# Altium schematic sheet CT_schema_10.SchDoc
size 226 x 144 mm
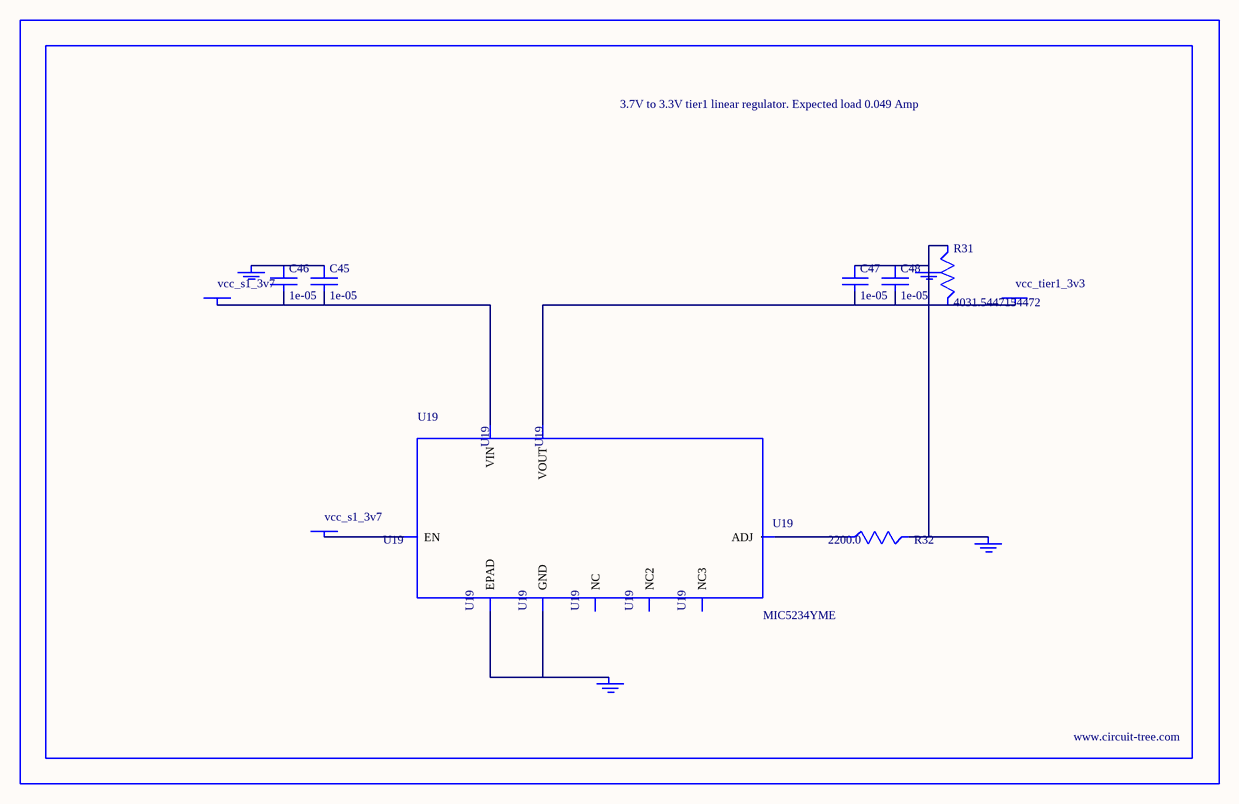
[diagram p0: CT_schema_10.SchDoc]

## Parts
BORDER9  (no value)
C45  1e-05  [C1210]
C46  1e-05  [C1210]
C47  1e-05  [C1210]
C48  1e-05  [C1210]
GND_INSTANCE_9_0  (no value)
GND_INSTANCE_9_1  (no value)
GND_INSTANCE_9_2  (no value)
GND_INSTANCE_9_3  (no value)
POWER_INSTANCE_9_0  vcc_tier1_3v3
POWER_INSTANCE_9_1  vcc_s1_3v7
POWER_INSTANCE_9_2  vcc_s1_3v7
R31  4031.5447154472  [R0603]
R32  2200.0  [R0603]
U19  MIC5234YME  [SOIC-8_EP]

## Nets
NetC45_1: C45.1 C46.1 GND_INSTANCE_9_3.0(GND)
NetC45_2: C45.2 C46.2 POWER_INSTANCE_9_2.0(PWR) U19.8(VIN)
NetC47_1: C47.1 C48.1 GND_INSTANCE_9_0.0(GND) GND_INSTANCE_9_1.0(GND) R31.1 R32.2
NetC47_2: C47.2 C48.2 POWER_INSTANCE_9_0.0(PWR) R31.2 U19.1(VOUT)
NetGND_INSTANCE_9_2_0: GND_INSTANCE_9_2.0(GND) U19.7(GND) U19.EPAD
NetPOWER_INSTANCE_9_1_0: POWER_INSTANCE_9_1.0(PWR) U19.5(EN)
NetR32_1: R32.1 U19.4(ADJ)

Not connected (* = marked no-connect by the designer): U19 2(NC) 3(NC2) 6(NC3)

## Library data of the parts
BORDER9 = BORDER_PAGE9
C45-C48 = C1210C106K5PACTU
GND_INSTANCE_9_0-GND_INSTANCE_9_3 = GND
POWER_INSTANCE_9_0-POWER_INSTANCE_9_2 = PWR
R31 = R31
R32 = RC0603JR-072K2L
